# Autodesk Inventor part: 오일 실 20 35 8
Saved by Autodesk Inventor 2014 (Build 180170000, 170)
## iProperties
Created: 2026-05
Part Number: 오일 실 20 35 8
Material: 일반
Document SubType Name: Modeling
Designer: dg
Density: 1 g/cm^3
Appearance: 기본값
Author: dg
Author: jhkim
Description: 오일-실
Creation Date: 2026-04-23
Sending System: Autodesk Inventor 2027
Preprocessor: ST-DEVELOPER v20.1
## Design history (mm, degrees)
node "오일 실 20 35 81"
body "Solid1"
node "기준1"
